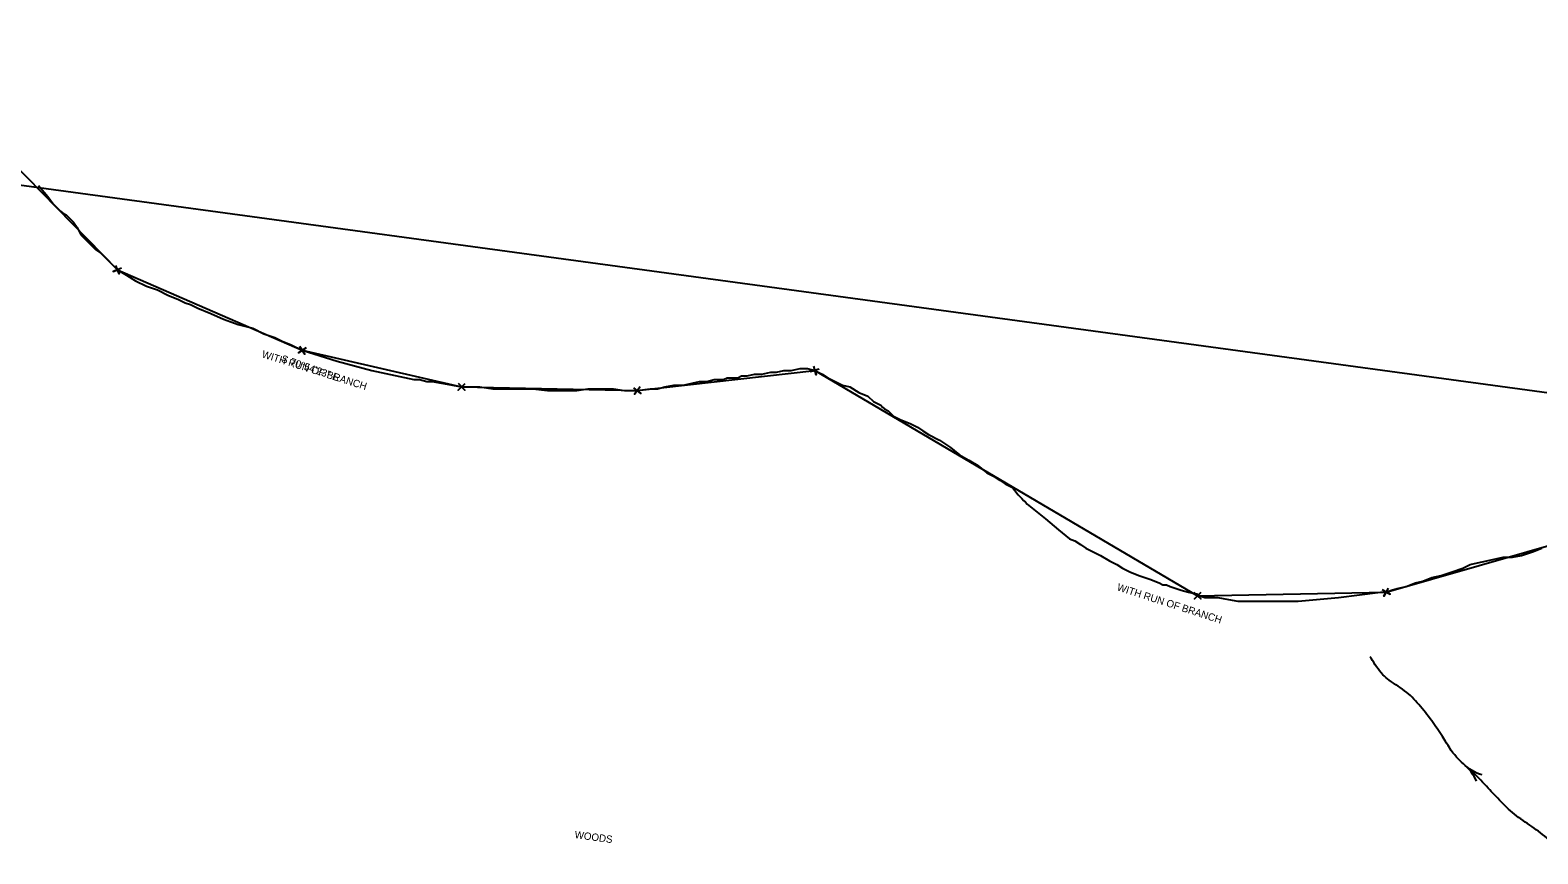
# Model space of a CAD drawing. Extents: x 2627243 to 2636458, y 566398 to 571062.
# Drawn here: x 2634573 to 2635397, y 569301 to 569751 of the extents above; entities that cross this region are included whole.
import ezdxf

# ---------------------------------------------------------------- set-up
doc = ezdxf.new("R2010")
doc.units = 0
for name, color, linetype in [('Exist Hydro Jurisdictional Stream or Body of Water', 7, 'Continuous'), ('Exist Hydro Stream Flow Arrow CELL', 7, 'Continuous'), ('Exist Hydro Stream or Body of Water', 7, 'Continuous'), ('Exist Property Corner CELL', 7, 'Continuous'), ('Exist Property Line', 7, 'Continuous'), ('Exist Property Line Text', 7, 'Continuous'), ('Exist Vegetation Woods Line Text', 7, 'Continuous'), ('Scratch_Level_1', 7, 'Continuous'), ('Scratch_Level_2', 7, 'Continuous')]:
    doc.layers.add(name, color=color, linetype=linetype)

# ---------------------------------------------------------------- blocks, each defined once
blk = doc.blocks.new('EXIST HYDRO STREAM FLOW ARROW')
at = {"layer": 'Exist Hydro Stream Flow Arrow CELL'}
blk.add_line((0, 0), (0, 0), dxfattribs=at)
for points in [[(-0.1, 0.04575), (-0.07325, 0.03375), (-0.04475, 0.0245), (-0.0165, 0.01575), (0.01175, 0.0095), (0.041, 0.00475), (0.07075, 0.0015), (0.1, 0)], [(-0.1, -0.04575), (-0.07325, -0.03375), (-0.04475, -0.0245), (-0.0165, -0.01575), (0.01175, -0.0095), (0.041, -0.00475), (0.07075, -0.0015), (0.1, 0)]]:
    blk.add_lwpolyline(points, dxfattribs=at)

msp = doc.modelspace()

# ---------------------------------------------------------------- linework, layer by layer
at = {"layer": 'Exist Hydro Jurisdictional Stream or Body of Water'}
msp.add_spline([(2634439.26, 569571.19), (2634439.59, 569567.51), (2634440.97, 569553.79), (2634439.58, 569543.4), (2634438.39, 569535.28), (2634439.25, 569529.24), (2634442.01, 569520.57), (2634446.12, 569510.93), (2634451.13, 569500.07), (2634455.3, 569490.19), (2634459.75, 569478.75), (2634463.32, 569469.08), (2634467.91, 569457.55), (2634471.65, 569447.03), (2634476.22, 569436.22), (2634476.14, 569426), (2634480.26, 569412.99), (2634486.48, 569403.77), (2634490.89, 569393.2), (2634498.99, 569385.5), (2634504, 569375.33), (2634510.06, 569363.23), (2634514.79, 569352.59), (2634523.21, 569338.71), (2634529.54, 569329.23), (2634534.99, 569318.17), (2634540.14, 569307.26), (2634544.47, 569296.7), (2634548.36, 569286.33), (2634552.93, 569273.85), (2634556.48, 569264.02), (2634560.09, 569255.14), (2634586.41, 569214.21)], degree=3, dxfattribs=at)
at = {"layer": 'Exist Hydro Stream or Body of Water'}
msp.add_spline([(2635697.19, 569078.83), (2635685.87, 569081.45), (2635674.49, 569085.48), (2635667.56, 569087.33), (2635657.56, 569088.51), (2635646.68, 569091.41), (2635635.64, 569093.58), (2635624.6, 569095.76), (2635614.15, 569098.3), (2635603.99, 569102.68), (2635594.03, 569106.77), (2635586.06, 569109.63), (2635573.31, 569115.37), (2635553.36, 569124.05), (2635543.06, 569129.98), (2635533.49, 569135.75), (2635528.08, 569139.8), (2635517.95, 569144.81), (2635507.58, 569149.87), (2635501.44, 569154.08), (2635498.43, 569156.94), (2635496.5, 569160.68), (2635495.47, 569164.98), (2635495.61, 569175.98), (2635498.12, 569186.82), (2635499.57, 569198.03), (2635499.13, 569202.7), (2635495.1, 569213.78), (2635491.03, 569225.25), (2635485.76, 569235.35), (2635480.39, 569243.95), (2635473.56, 569252.26), (2635465.97, 569259.47), (2635456.71, 569267.7), (2635447.75, 569274.47), (2635439.28, 569280.11), (2635429.97, 569286.45), (2635421.69, 569293.44), (2635412.25, 569301.97), (2635402.95, 569308.94), (2635393.65, 569315.92), (2635384.06, 569322.71), (2635375.95, 569330.42), (2635368.8, 569337.91), (2635360.28, 569346.6), (2635352.45, 569353.87), (2635345.44, 569364.12), (2635339.77, 569372.54), (2635332.72, 569381.53), (2635325.24, 569389.22), (2635315.74, 569395.86), (2635312.24, 569398.83), (2635305.82, 569407.8), (2635305.35, 569408.54)], degree=3, dxfattribs=at)
at = {"layer": 'Exist Property Corner CELL'}
for p, q in [((2634621, 569620), (2634621, 569620)), ((2634722, 569576), (2634722, 569576)), ((2635002, 569565), (2635002, 569565)), ((2634809, 569556), (2634809, 569556)), ((2634905, 569554), (2634905, 569554)), ((2635211, 569442), (2635211, 569442)), ((2635314, 569444), (2635314, 569444))]:
    msp.add_line(p, q, dxfattribs=at)
for points in [[(2634623.33, 569620.91), (2634618.67, 569619.09), (2634621, 569620), (2634621.91, 569617.67), (2634620.09, 569622.33)], [(2634724.12, 569577.33), (2634719.88, 569574.67), (2634722, 569576), (2634723.33, 569573.88), (2634720.67, 569578.12)], [(2635004.42, 569565.63), (2634999.58, 569564.37), (2635002, 569565), (2635002.63, 569562.58), (2635001.37, 569567.42)], [(2634810.8, 569557.73), (2634807.2, 569554.27), (2634809, 569556), (2634810.73, 569554.2), (2634807.27, 569557.8)], [(2634906.56, 569555.96), (2634903.44, 569552.04), (2634905, 569554), (2634906.96, 569552.44), (2634903.04, 569555.56)], [(2635212.73, 569443.8), (2635209.27, 569440.2), (2635211, 569442), (2635212.8, 569440.27), (2635209.2, 569443.73)], [(2635315.21, 569446.19), (2635312.79, 569441.81), (2635314, 569444), (2635316.19, 569442.79), (2635311.81, 569445.21)]]:
    msp.add_lwpolyline(points, dxfattribs=at)
at = {"layer": 'Exist Property Line'}
for p, q in [((2634521, 569722), (2634621, 569620)), ((2634621, 569620), (2634722, 569576)), ((2634722, 569576), (2634809, 569556)), ((2634905, 569554), (2635002, 569565)), ((2635002, 569565), (2635211, 569442)), ((2634809, 569556), (2634905, 569554)), ((2635314, 569444), (2635436, 569479)), ((2635211, 569442), (2635314, 569444))]:
    msp.add_line(p, q, dxfattribs=at)
at = {"layer": 'Scratch_Level_1'}
for p, q in [((2634578, 569666), (2634583, 569660)), ((2634583, 569660), (2634586, 569656)), ((2634586, 569656), (2634590, 569652)), ((2634590, 569652), (2634591, 569651)), ((2634591, 569651), (2634593, 569650)), ((2634593, 569650), (2634595, 569648)), ((2634595, 569648), (2634597, 569646)), ((2634597, 569646), (2634599, 569643)), ((2634599, 569643), (2634601, 569639)), ((2634601, 569639), (2634605, 569635)), ((2634605, 569635), (2634609, 569631)), ((2634609, 569631), (2634612, 569629)), ((2634612, 569629), (2634615, 569626)), ((2634615, 569626), (2634618, 569623)), ((2634618, 569623), (2634621, 569620)), ((2634621, 569620), (2634626, 569617)), ((2634626, 569617), (2634631, 569614)), ((2634631, 569614), (2634637, 569611)), ((2634637, 569611), (2634643, 569609)), ((2634643, 569609), (2634649, 569606)), ((2634649, 569606), (2634654, 569604)), ((2634654, 569604), (2634658, 569602)), ((2634658, 569602), (2634661, 569601)), ((2634661, 569601), (2634665, 569599)), ((2634665, 569599), (2634672, 569596)), ((2634672, 569596), (2634679, 569593)), ((2634679, 569593), (2634687, 569590)), ((2634687, 569590), (2634695, 569588)), ((2634695, 569588), (2634701, 569585)), ((2634701, 569585), (2634707, 569583)), ((2634707, 569583), (2634711, 569581)), ((2634711, 569581), (2634716, 569579)), ((2634716, 569579), (2634722, 569576)), ((2634722, 569576), (2634741, 569570)), ((2634741, 569570), (2634760, 569565)), ((2634989, 569565), (2634994, 569566)), ((2634994, 569566), (2634998, 569566)), ((2634998, 569566), (2635002, 569565)), ((2634760, 569565), (2634783, 569560)), ((2634783, 569560), (2634786, 569560)), ((2634786, 569560), (2634790, 569559)), ((2634790, 569559), (2634793, 569559)), ((2634793, 569559), (2634798, 569558)), ((2634798, 569558), (2634804, 569557)), ((2634930, 569557), (2634935, 569558)), ((2634935, 569558), (2634939, 569559)), ((2634939, 569559), (2634943, 569559)), ((2634943, 569559), (2634947, 569560)), ((2634947, 569560), (2634952, 569560)), ((2634952, 569560), (2634954, 569561)), ((2634954, 569561), (2634957, 569561)), ((2634957, 569561), (2634960, 569561)), ((2634960, 569561), (2634962, 569562)), ((2634962, 569562), (2634963, 569562)), ((2634963, 569562), (2634965, 569562)), ((2634965, 569562), (2634969, 569563)), ((2634969, 569563), (2634973, 569563)), ((2634973, 569563), (2634978, 569564)), ((2634978, 569564), (2634981, 569564)), ((2634981, 569564), (2634985, 569565)), ((2634985, 569565), (2634989, 569565)), ((2635002, 569565), (2635006, 569563)), ((2635006, 569563), (2635009, 569561)), ((2635009, 569561), (2635013, 569559)), ((2635013, 569559), (2635017, 569557)), ((2634804, 569557), (2634809, 569556)), ((2634809, 569556), (2634814, 569556)), ((2634814, 569556), (2634819, 569556)), ((2634819, 569556), (2634826, 569555)), ((2634826, 569555), (2634832, 569555)), ((2634832, 569555), (2634837, 569555)), ((2634837, 569555), (2634841, 569555)), ((2634841, 569555), (2634848, 569555)), ((2634848, 569555), (2634856, 569554)), ((2634856, 569554), (2634864, 569554)), ((2634864, 569554), (2634868, 569554)), ((2634868, 569554), (2634872, 569554)), ((2634872, 569554), (2634878, 569555)), ((2634878, 569555), (2634883, 569555)), ((2634883, 569555), (2634888, 569555)), ((2634888, 569555), (2634892, 569555)), ((2634892, 569555), (2634898, 569554)), ((2634898, 569554), (2634905, 569554)), ((2634905, 569554), (2634912, 569555)), ((2634912, 569555), (2634916, 569555)), ((2634916, 569555), (2634920, 569556)), ((2634920, 569556), (2634925, 569557)), ((2634925, 569557), (2634930, 569557)), ((2635017, 569557), (2635021, 569556)), ((2635021, 569556), (2635026, 569553)), ((2635026, 569553), (2635031, 569551)), ((2635031, 569551), (2635034, 569548)), ((2635034, 569548), (2635038, 569546)), ((2635038, 569546), (2635039, 569545)), ((2635039, 569545), (2635040, 569544)), ((2635040, 569544), (2635042, 569543)), ((2635042, 569543), (2635045, 569540)), ((2635045, 569540), (2635049, 569538)), ((2635049, 569538), (2635054, 569536)), ((2635054, 569536), (2635058, 569534)), ((2635058, 569534), (2635061, 569532)), ((2635061, 569532), (2635064, 569530)), ((2635064, 569530), (2635070, 569527)), ((2635070, 569527), (2635076, 569523)), ((2635076, 569523), (2635081, 569519)), ((2635081, 569519), (2635086, 569516)), ((2635086, 569516), (2635091, 569513)), ((2635091, 569513), (2635096, 569509)), ((2635096, 569509), (2635100, 569507)), ((2635100, 569507), (2635103, 569505)), ((2635103, 569505), (2635106, 569503)), ((2635106, 569503), (2635110, 569501)), ((2635110, 569501), (2635113, 569497)), ((2635113, 569497), (2635115, 569495)), ((2635115, 569495), (2635116, 569494)), ((2635116, 569494), (2635117, 569493)), ((2635117, 569493), (2635118, 569492)), ((2635118, 569492), (2635128, 569484)), ((2635128, 569484), (2635135, 569478)), ((2635135, 569478), (2635141, 569473)), ((2635141, 569473), (2635144, 569472)), ((2635144, 569472), (2635147, 569470)), ((2635147, 569470), (2635150, 569468)), ((2635150, 569468), (2635154, 569466)), ((2635394, 569466), (2635399, 569468)), ((2635154, 569466), (2635158, 569464)), ((2635158, 569464), (2635163, 569461)), ((2635163, 569461), (2635167, 569459)), ((2635167, 569459), (2635170, 569457)), ((2635356, 569457), (2635360, 569459)), ((2635360, 569459), (2635364, 569460)), ((2635364, 569460), (2635369, 569461)), ((2635369, 569461), (2635373, 569462)), ((2635373, 569462), (2635378, 569463)), ((2635378, 569463), (2635383, 569463)), ((2635383, 569463), (2635388, 569464)), ((2635388, 569464), (2635394, 569466)), ((2635170, 569457), (2635174, 569455)), ((2635174, 569455), (2635179, 569453)), ((2635179, 569453), (2635185, 569451)), ((2635185, 569451), (2635190, 569449)), ((2635330, 569449), (2635334, 569450)), ((2635334, 569450), (2635339, 569452)), ((2635339, 569452), (2635344, 569453)), ((2635344, 569453), (2635350, 569455)), ((2635350, 569455), (2635356, 569457)), ((2635190, 569449), (2635192, 569448)), ((2635192, 569448), (2635194, 569448)), ((2635194, 569448), (2635196, 569447)), ((2635196, 569447), (2635202, 569445)), ((2635202, 569445), (2635206, 569444)), ((2635206, 569444), (2635210, 569443)), ((2635210, 569443), (2635211, 569443)), ((2635211, 569443), (2635211, 569442)), ((2635211, 569442), (2635212, 569442)), ((2635212, 569442), (2635215, 569441)), ((2635288, 569441), (2635311, 569444)), ((2635311, 569444), (2635314, 569444)), ((2635314, 569444), (2635317, 569445)), ((2635317, 569445), (2635320, 569446)), ((2635320, 569446), (2635325, 569447)), ((2635325, 569447), (2635330, 569449)), ((2635215, 569441), (2635218, 569441)), ((2635218, 569441), (2635222, 569441)), ((2635222, 569441), (2635228, 569440)), ((2635228, 569440), (2635233, 569439)), ((2635233, 569439), (2635238, 569439)), ((2635238, 569439), (2635240, 569439)), ((2635240, 569439), (2635243, 569439)), ((2635243, 569439), (2635245, 569439)), ((2635245, 569439), (2635266, 569439)), ((2635266, 569439), (2635288, 569441))]:
    msp.add_line(p, q, dxfattribs=at)
at = {"layer": 'Scratch_Level_2'}
msp.add_lwpolyline([(2633945.71, 569750.8), (2635590.54, 569527.29), (2635449.16, 568486.85), (2633804.33, 568710.36)], close=True, dxfattribs=at)

# ---------------------------------------------------------------- block references
at = {"layer": 'Exist Hydro Stream Flow Arrow CELL', "xscale": 50.00000000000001, "yscale": 50, "rotation": 138.4905361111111}
msp.add_blockref('EXIST HYDRO STREAM FLOW ARROW', (2635361.16, 569345.72), dxfattribs=at)

# ---------------------------------------------------------------- texts
at = {"layer": 'Exist Property Line Text'}
for rotation, p in [(342.47443, (2634699.58, 569572.22)), (342.14322, (2635166.7, 569445))]:
    msp.add_text('WITH RUN OF BRANCH', height=4, rotation=rotation, dxfattribs=at).set_placement(p)
at = {"layer": 'Exist Vegetation Woods Line Text'}
msp.add_text('WOODS', height=4, rotation=352.32218, dxfattribs=at).set_placement((2634870.58, 569309.65))
at = {"layer": 'Scratch_Level_1'}
msp.add_text('S 70%%D54\'23" E', height=4, rotation=340.90651, dxfattribs=at).set_placement((2634710.17, 569569.8))

doc.saveas('drawing.dxf')
